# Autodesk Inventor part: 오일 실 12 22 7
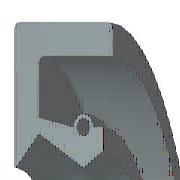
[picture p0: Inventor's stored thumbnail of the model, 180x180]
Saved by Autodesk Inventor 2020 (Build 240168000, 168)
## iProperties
Created: 2012-02
Part Number: 오일 실 12 22 7
Material: 고무
Description: 오일-실
Document SubType Name: Modeling
Standard: KS B 2804
Designer: mduedu
Standards Organization: KS
Language: ko-KR
Size Designation: D - 12 22 7
Categories: <MemberInstance><Categories><Category DisplayName="샤프트 부품" InternalName="7f7aeb1f-a693-4053-b835-cee3144e0d98" Mnemonic="SHFT"><Category DisplayName="실링" Intern
Density: 0.93 g/cm^3
Mass: 1.25383 g
Surface Area: 18.4996 cm^2
Volume: 1.3482 cm^3
Appearance: 고무 - 검은색 - 버전 1.1
IsCustomPart: 1
Author: mduedu
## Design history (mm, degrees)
revolve "본체" stored, may be unused: angle "d17" = 90 deg
revolve "스프링1" stored, may be unused: angle "d18" = 90 deg
body "Solid1"
sketch "스케치1"
  geometry: L1 (0, 11)-(7, 11); L2 (7, 9.25)-(1.75, 9.25); L3 (1.75, 7.75)-(4.9, 6); L4 (4.9, 6)-(0, 6); L5 (0, 0)-(9.586, 0) reference; L6 (4.9, 6)-(6.3, 6.875); L7 (0, 18)-(0, -3) reference; L8 (-1.941, 0)-(11.507, 0) reference; L9 (4.2, 8.1)-(1.75, 8.59); L10 (1.75, 8.59)-(1.75, 9.25); L11 (0, 11)-(0, 6.088); L12 (4.9, 6)-(0, 6); L13 (1.75, 7.75)-(0.152, 6.028); L14 (7, 11)-(7, 9.25); L15 (5.6, 8.1)-(6.3, 8.1); L16 (6.3, 8.1)-(6.3, 6.875); C1 r 0.455 at (4.9, 8.1); A1 r 0.7 centre (4.9, 8.1) between (5.6, 8.1) and (4.2, 8.1); A2 r 0.088 centre (0.088, 6.088) between (0, 6.088) and (0.152, 6.028); 1 further point
  constraints: 28 end point, 5 horizontal alignment, 5 point on line, 4 point on circle, 4 vertical alignment, 3 centre point, 3 tangent, 2 collinear, 2 horizontal, 2 perpendicular, 1 coincident, 1 parallel
  dimensions: "d0" = 22 diameter of L1 L5 (= SD2); "d1" = 1.75 distance of L1.end L2.start (= SD); "d2" = 0.91 diameter of C1 (= SPDI); "d3" = 1.4 diameter of A1 (= SPDA); "d4" = 12 diameter of L3.end L5 (= NND); "d5" = 15.5 diameter of L3.start L5 (= TKDM); "d7" = 17.18 diameter of L9.end L5 (= TKDM + 0.24 x SWDT); "d8" = 1.75 distance between parallel lines of L11 L10 (= SD); "d9" = 4.9 distance from line of L11 C1.centre (= SPDST); "d10" = 16.2 diameter of C1.centre L5 (= HLDM); "d11" = 0.0875 radius of A2 (= 0.25 x LAB); "d12" = 6.3 distance between parallel lines of L11 L16 (= SDI); "d13" = 13.75 diameter of L6.end L5 (= ABDM); "d14" = 7 distance from line of L11 L1.end (= SWDT)
fillet "모깎기1" dims "d6" = 0.3 (= RR)
other parameters: "SD2" = 22 [user parameter; used in 1 equation term], "SWDT" = 7 [user parameter; used in 2 equation terms], "RR" = 0.3 [user parameter; used in 1 equation term], "SD" = 1.75 [user parameter; used in 2 equation terms], "NND" = 12 [user parameter; used in 1 equation term], "SPDA" = 1.4 [user parameter; used in 1 equation term], "SPDI" = 0.91 [user parameter; used in 1 equation term], "TKDM" = 15.5 [user parameter; used in 2 equation terms], "HLDM" = 16.2 [user parameter; used in 1 equation term], "ABDM" = 13.75 [user parameter; used in 1 equation term], "SDI" = 6.3 [user parameter; used in 1 equation term], "SPDST" = 4.9 [user parameter; used in 1 equation term], "LAB" = 0.35 [user parameter; used in 1 equation term], "d15" = 0, "d16" = 0, "d19" = 0
